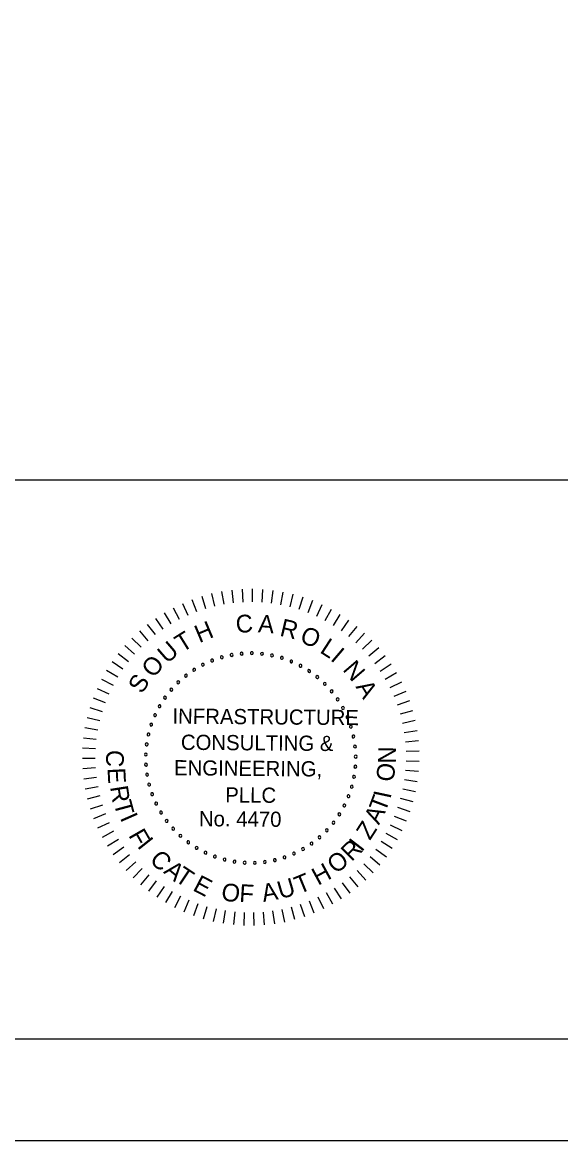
# Model space of a CAD drawing. Extents: x 1970675.2 to 1970711.3, y 796145.2 to 796167.2.
# Drawn here: x 1970700.45 to 1970703.09, y 796145.25 to 796150.75 of the extents above; entities that cross this region are included whole.
import ezdxf

# ---------------------------------------------------------------- set-up
doc = ezdxf.new("R2010")
doc.units = 0
for name, color, linetype in [('BR_BORDER LINES', 7, 'Continuous'), ('BR_TEXT', 7, 'Continuous'), ('Level 31', 7, 'Continuous')]:
    doc.layers.add(name, color=color, linetype=linetype)

msp = doc.modelspace()

# ---------------------------------------------------------------- linework, layer by layer
at = {"layer": 'BR_BORDER LINES'}
for p, q in [((1970697.8703, 796148.4964), (1970703.2355, 796148.4964)), ((1970677.0698, 796145.7463), (1970710.7358, 796145.7463))]:
    msp.add_line(p, q, dxfattribs=at)
at = {"layer": 'BR_TEXT'}
for p, q in [((1970701.4262, 796147.9473), (1970701.4372, 796147.8846)), ((1970701.4761, 796147.9545), (1970701.4834, 796147.8913)), ((1970701.5265, 796147.9587), (1970701.5298, 796147.8951)), ((1970701.5769, 796147.9597), (1970701.5764, 796147.8961)), ((1970701.6274, 796147.9577), (1970701.623, 796147.8942)), ((1970701.6776, 796147.9526), (1970701.6693, 796147.8895)), ((1970701.2802, 796147.9077), (1970701.3025, 796147.8481)), ((1970701.328, 796147.9239), (1970701.3466, 796147.863)), ((1970701.3767, 796147.9371), (1970701.3916, 796147.8752)), ((1970701.7274, 796147.9445), (1970701.7153, 796147.882)), ((1970701.7767, 796147.9333), (1970701.7608, 796147.8717)), ((1970701.8251, 796147.9192), (1970701.8055, 796147.8586)), ((1970701.8726, 796147.9021), (1970701.8494, 796147.8428)), ((1970701.1439, 796147.8422), (1970701.1766, 796147.7876)), ((1970701.1879, 796147.8668), (1970701.2173, 796147.8103)), ((1970701.2334, 796147.8887), (1970701.2593, 796147.8305)), ((1970701.919, 796147.8822), (1970701.8922, 796147.8244)), ((1970701.9641, 796147.8594), (1970701.9338, 796147.8034)), ((1970701.0606, 796147.7852), (1970701.0998, 796147.735)), ((1970701.1014, 796147.8149), (1970701.1374, 796147.7625)), ((1970702.0077, 796147.834), (1970701.974, 796147.78)), ((1970702.0497, 796147.8059), (1970702.0128, 796147.7541)), ((1970701.0217, 796147.7529), (1970701.0639, 796147.7052)), ((1970702.0899, 796147.7754), (1970702.0499, 796147.7259)), ((1970702.1281, 796147.7424), (1970702.0852, 796147.6954)), ((1970700.9502, 796147.6817), (1970700.9979, 796147.6395)), ((1970700.9849, 796147.7184), (1970701.0299, 796147.6734)), ((1970702.1643, 796147.7072), (1970702.1186, 796147.6629)), ((1970700.9179, 796147.643), (1970700.968, 796147.6037)), ((1970702.1982, 796147.6699), (1970702.1499, 796147.6284)), ((1970702.2299, 796147.6305), (1970702.1791, 796147.5921)), ((1970700.8879, 796147.6023), (1970700.9404, 796147.5662)), ((1970702.259, 796147.5893), (1970702.206, 796147.5541)), ((1970700.8358, 796147.5159), (1970700.8922, 796147.4865)), ((1970700.8605, 796147.5599), (1970700.9151, 796147.5271)), ((1970702.2856, 796147.5464), (1970702.2305, 796147.5145)), ((1970700.8137, 796147.4705), (1970700.8719, 796147.4445)), ((1970702.3095, 796147.5019), (1970702.2526, 796147.4734)), ((1970702.3307, 796147.4561), (1970702.2722, 796147.4311)), ((1970700.7945, 796147.4238), (1970700.8541, 796147.4014)), ((1970702.3491, 796147.4091), (1970702.2891, 796147.3877)), ((1970700.7782, 796147.3761), (1970700.839, 796147.3574)), ((1970702.3645, 796147.361), (1970702.3033, 796147.3433)), ((1970700.7648, 796147.3274), (1970700.8267, 796147.3124)), ((1970702.377, 796147.3121), (1970702.3148, 796147.2982)), ((1970700.7543, 796147.278), (1970700.817, 796147.2668)), ((1970702.3864, 796147.2625), (1970702.3236, 796147.2524)), ((1970700.7426, 796147.1777), (1970700.8062, 796147.1743)), ((1970700.747, 796147.228), (1970700.8102, 796147.2207)), ((1970702.3929, 796147.2124), (1970702.3295, 796147.2062)), ((1970700.7414, 796147.1273), (1970700.8051, 796147.1277)), ((1970702.3963, 796147.1621), (1970702.3326, 796147.1597)), ((1970700.7432, 796147.0768), (1970700.8067, 796147.0812)), ((1970702.3965, 796147.1116), (1970702.3329, 796147.1131)), ((1970700.7481, 796147.0266), (1970700.8113, 796147.0348)), ((1970702.3879, 796147.011), (1970702.3249, 796147.0203)), ((1970702.3938, 796147.0612), (1970702.3303, 796147.0666)), ((1970700.7561, 796146.9767), (1970700.8186, 796146.9888)), ((1970702.379, 796146.9613), (1970702.3167, 796146.9744)), ((1970700.7671, 796146.9275), (1970700.8287, 796146.9433)), ((1970702.3671, 796146.9123), (1970702.3057, 796146.9291)), ((1970700.781, 796146.8789), (1970700.8416, 796146.8985)), ((1970700.7979, 796146.8314), (1970700.8572, 796146.8546)), ((1970702.3522, 796146.864), (1970702.2919, 796146.8846)), ((1970700.8177, 796146.7849), (1970700.8755, 796146.8117)), ((1970702.3138, 796146.7707), (1970702.2564, 796146.7985)), ((1970702.3344, 796146.8168), (1970702.2755, 796146.841)), ((1970700.8403, 796146.7397), (1970700.8963, 796146.77)), ((1970702.2904, 796146.726), (1970702.2348, 796146.7572)), ((1970700.8655, 796146.696), (1970700.9196, 796146.7297)), ((1970700.8934, 796146.654), (1970700.9453, 796146.6908)), ((1970702.2643, 796146.6828), (1970702.2107, 796146.7173)), ((1970700.9238, 796146.6137), (1970700.9734, 796146.6536)), ((1970702.2044, 796146.6015), (1970702.1555, 796146.6423)), ((1970702.2356, 796146.6412), (1970702.1843, 796146.6789)), ((1970700.9566, 796146.5753), (1970701.0037, 796146.6182)), ((1970700.9917, 796146.539), (1970701.0361, 796146.5847)), ((1970702.1351, 796146.5281), (1970702.0915, 796146.5745)), ((1970702.1709, 796146.5638), (1970702.1245, 796146.6074)), ((1970701.0289, 796146.5049), (1970701.0704, 796146.5532)), ((1970701.0682, 796146.4731), (1970701.1066, 796146.5239)), ((1970702.0973, 796146.4948), (1970702.0566, 796146.5437)), ((1970701.1093, 796146.4438), (1970701.1446, 796146.4968)), ((1970701.1521, 796146.4171), (1970701.1841, 796146.4721)), ((1970701.9725, 796146.4093), (1970701.9414, 796146.4648)), ((1970702.0158, 796146.4352), (1970701.9813, 796146.4888)), ((1970702.0574, 796146.4637), (1970702.0198, 796146.5151)), ((1970701.1965, 796146.393), (1970701.225, 796146.4499)), ((1970701.2422, 796146.3716), (1970701.2673, 796146.4302)), ((1970701.2892, 796146.3531), (1970701.3106, 796146.4131)), ((1970701.8342, 796146.3479), (1970701.8137, 796146.4082)), ((1970701.8815, 796146.3656), (1970701.8574, 796146.4245)), ((1970701.9276, 796146.386), (1970701.9, 796146.4434)), ((1970701.3372, 796146.3375), (1970701.3549, 796146.3986)), ((1970701.386, 796146.3248), (1970701.4001, 796146.3869)), ((1970701.4356, 796146.3152), (1970701.4458, 796146.378)), ((1970701.4856, 796146.3086), (1970701.492, 796146.3719)), ((1970701.536, 796146.305), (1970701.5385, 796146.3686)), ((1970701.5865, 796146.3045), (1970701.5851, 796146.3682)), ((1970701.6369, 796146.3071), (1970701.6316, 796146.3706)), ((1970701.6871, 796146.3128), (1970701.6779, 796146.3758)), ((1970701.7368, 796146.3215), (1970701.7238, 796146.3838)), ((1970701.7859, 796146.3332), (1970701.7691, 796146.3947))]:
    msp.add_line(p, q, dxfattribs=at)
for centre, start, end in [((1970701.4268, 796147.6235), 16.1422, 196.1422), ((1970701.4268, 796147.6235), 196.1422, 16.1422), ((1970701.4753, 796147.635), 10.6038, 190.6038), ((1970701.4753, 796147.635), 190.6038, 10.6038), ((1970701.5247, 796147.6417), 5.0653, 185.0653), ((1970701.5247, 796147.6417), 185.0653, 5.0653), ((1970701.5745, 796147.6436), 359.5268, 179.5268), ((1970701.5745, 796147.6436), 179.5268, 359.5268), ((1970701.6242, 796147.6407), 173.9884, 353.9884), ((1970701.6242, 796147.6407), 353.9884, 173.9884), ((1970701.6735, 796147.6329), 168.4499, 348.4499), ((1970701.6735, 796147.6329), 348.4499, 168.4499), ((1970701.7217, 796147.6205), 162.9114, 342.9114), ((1970701.7217, 796147.6205), 342.9114, 162.9114), ((1970701.291, 796147.5621), 32.7576, 212.7576), ((1970701.291, 796147.5621), 212.7576, 32.7576), ((1970701.3343, 796147.587), 27.2191, 207.2191), ((1970701.3343, 796147.587), 207.2191, 27.2191), ((1970701.3797, 796147.6075), 21.6807, 201.6807), ((1970701.3797, 796147.6075), 201.6807, 21.6807), ((1970701.7686, 796147.6035), 157.373, 337.373), ((1970701.7686, 796147.6035), 337.373, 157.373), ((1970701.8135, 796147.582), 151.8345, 331.8345), ((1970701.8135, 796147.582), 331.8345, 151.8345), ((1970701.8562, 796147.5563), 326.2961, 146.2961), ((1970701.2128, 796147.5006), 43.8345, 223.8345), ((1970701.2504, 796147.5333), 38.2961, 218.2961), ((1970701.2504, 796147.5333), 218.2961, 38.2961), ((1970701.8562, 796147.5563), 146.2961, 326.2961), ((1970701.8962, 796147.5266), 140.7576, 320.7576), ((1970701.8962, 796147.5266), 320.7576, 140.7576), ((1970701.1785, 796147.4645), 49.373, 229.373), ((1970701.1785, 796147.4645), 229.373, 49.373), ((1970701.2128, 796147.5006), 223.8345, 43.8345), ((1970701.9332, 796147.4932), 135.2191, 315.2191), ((1970701.9332, 796147.4932), 315.2191, 135.2191), ((1970701.9668, 796147.4564), 129.6807, 309.6807), ((1970701.9668, 796147.4564), 309.6807, 129.6807), ((1970701.1478, 796147.4252), 54.9114, 234.9114), ((1970701.1478, 796147.4252), 234.9114, 54.9114), ((1970701.9966, 796147.4165), 124.1422, 304.1422), ((1970701.9966, 796147.4165), 304.1422, 124.1422), ((1970701.0986, 796147.3387), 65.9884, 245.9884), ((1970701.0986, 796147.3387), 245.9884, 65.9884), ((1970701.1211, 796147.3831), 60.4499, 240.4499), ((1970701.1211, 796147.3831), 240.4499, 60.4499), ((1970702.0225, 796147.3739), 118.6038, 298.6038), ((1970702.0225, 796147.3739), 298.6038, 118.6038), ((1970701.0804, 796147.2923), 71.5268, 251.5268), ((1970701.0804, 796147.2923), 251.5268, 71.5268), ((1970702.0441, 796147.329), 113.0653, 293.0653), ((1970702.0441, 796147.329), 293.0653, 113.0653), ((1970702.0613, 796147.2822), 107.5268, 287.5268), ((1970702.0613, 796147.2822), 287.5268, 107.5268), ((1970701.0668, 796147.2443), 77.0653, 257.0653), ((1970701.0668, 796147.2443), 257.0653, 77.0653), ((1970702.0739, 796147.234), 101.9884, 281.9884), ((1970702.0739, 796147.234), 281.9884, 101.9884), ((1970701.0579, 796147.1953), 82.6038, 262.6038), ((1970701.0579, 796147.1953), 262.6038, 82.6038), ((1970702.0818, 796147.1848), 96.4499, 276.4499), ((1970702.0818, 796147.1848), 276.4499, 96.4499), ((1970701.0538, 796147.1456), 88.1422, 268.1422), ((1970701.0538, 796147.1456), 268.1422, 88.1422), ((1970702.0849, 796147.1351), 90.9114, 270.9114), ((1970702.0849, 796147.1351), 270.9114, 90.9114), ((1970701.0545, 796147.0958), 93.6807, 273.6807), ((1970701.0545, 796147.0958), 273.6807, 93.6807), ((1970702.0832, 796147.0853), 85.373, 265.373), ((1970702.0832, 796147.0853), 265.373, 85.373), ((1970701.06, 796147.0463), 99.2191, 279.2191), ((1970701.06, 796147.0463), 279.2191, 99.2191), ((1970702.0766, 796147.0359), 79.8345, 259.8345), ((1970702.0766, 796147.0359), 259.8345, 79.8345), ((1970701.0703, 796146.9975), 104.7576, 284.7576), ((1970701.0703, 796146.9975), 284.7576, 104.7576), ((1970701.0852, 796146.95), 290.2961, 110.2961), ((1970702.0654, 796146.9873), 74.2961, 254.2961), ((1970702.0654, 796146.9873), 254.2961, 74.2961), ((1970701.0852, 796146.95), 110.2961, 290.2961), ((1970701.1046, 796146.9041), 115.8345, 295.8345), ((1970701.1046, 796146.9041), 295.8345, 115.8345), ((1970702.0291, 796146.8946), 63.2191, 243.2191), ((1970702.0495, 796146.9401), 68.7576, 248.7576), ((1970702.0495, 796146.9401), 248.7576, 68.7576), ((1970701.1284, 796146.8603), 121.373, 301.373), ((1970701.1284, 796146.8603), 301.373, 121.373), ((1970702.0045, 796146.8513), 57.6807, 237.6807), ((1970702.0045, 796146.8513), 237.6807, 57.6807), ((1970702.0291, 796146.8946), 243.2191, 63.2191), ((1970701.1563, 796146.819), 126.9114, 306.9114), ((1970701.1563, 796146.819), 306.9114, 126.9114), ((1970701.9758, 796146.8106), 52.1422, 232.1422), ((1970701.9758, 796146.8106), 232.1422, 52.1422), ((1970701.188, 796146.7806), 132.4499, 312.4499), ((1970701.188, 796146.7806), 312.4499, 132.4499), ((1970701.2233, 796146.7454), 137.9884, 317.9884), ((1970701.2233, 796146.7454), 317.9884, 137.9884), ((1970701.9072, 796146.7384), 41.0653, 221.0653), ((1970701.9072, 796146.7384), 221.0653, 41.0653), ((1970701.9432, 796146.7728), 46.6038, 226.6038), ((1970701.9432, 796146.7728), 226.6038, 46.6038), ((1970701.2618, 796146.7138), 143.5268, 323.5268), ((1970701.2618, 796146.7138), 323.5268, 143.5268), ((1970701.3032, 796146.6861), 149.0653, 329.0653), ((1970701.3032, 796146.6861), 329.0653, 149.0653), ((1970701.8261, 796146.6807), 29.9884, 209.9884), ((1970701.8261, 796146.6807), 209.9884, 29.9884), ((1970701.8681, 796146.7076), 35.5268, 215.5268), ((1970701.8681, 796146.7076), 215.5268, 35.5268), ((1970701.3471, 796146.6625), 154.6038, 334.6038), ((1970701.3471, 796146.6625), 334.6038, 154.6038), ((1970701.3931, 796146.6432), 160.1422, 340.1422), ((1970701.3931, 796146.6432), 340.1422, 160.1422), ((1970701.4407, 796146.6285), 165.6807, 345.6807), ((1970701.4407, 796146.6285), 345.6807, 165.6807), ((1970701.6875, 796146.6259), 13.373, 193.373), ((1970701.6875, 796146.6259), 193.373, 13.373), ((1970701.7354, 796146.6397), 18.9114, 198.9114), ((1970701.7354, 796146.6397), 198.9114, 18.9114), ((1970701.7817, 796146.658), 24.4499, 204.4499), ((1970701.7817, 796146.658), 204.4499, 24.4499), ((1970701.4895, 796146.6184), 171.2191, 351.2191), ((1970701.4895, 796146.6184), 351.2191, 171.2191), ((1970701.539, 796146.6131), 356.7576, 176.7576), ((1970701.539, 796146.6131), 176.7576, 356.7576), ((1970701.5889, 796146.6126), 2.2961, 182.2961), ((1970701.5889, 796146.6126), 182.2961, 2.2961), ((1970701.6385, 796146.6169), 7.8345, 187.8345), ((1970701.6385, 796146.6169), 187.8345, 7.8345)]:
    msp.add_arc(centre, 0.00701, start, end, dxfattribs=at)
at = {"layer": 'Level 31'}
msp.add_lwpolyline([(1970675.2365, 796145.2464), (1970711.2364, 796145.2464), (1970711.2364, 796167.2463), (1970675.2365, 796167.2463)], close=True, dxfattribs=at)

# ---------------------------------------------------------------- texts
at = {"layer": 'BR_TEXT'}
for s, height, rotation, p in [('H', 0.0872, 22.7882, (1970701.3162, 796147.6927)), ('C', 0.0872, 4.7281, (1970701.499, 796147.7421)), ('A', 0.0872, 355.6981, (1970701.6035, 796147.7471)), ('R', 0.0872, 346.6681, (1970701.7077, 796147.7301)), ('T', 0.0872, 31.8182, (1970701.2313, 796147.6451)), ('O', 0.0872, 337.638, (1970701.8055, 796147.7003)), ('U', 0.0872, 40.8482, (1970701.158, 796147.589)), ('L', 0.0872, 327.108, (1970701.9043, 796147.6498)), ('O', 0.0872, 49.8782, (1970701.091, 796147.518)), ('I', 0.0872, 319.578, (1970701.9569, 796147.612)), ('N', 0.0872, 310.548, (1970702.0177, 796147.5612)), ('S', 0.0872, 58.9083, (1970701.0356, 796147.4398)), ('A', 0.0872, 301.5179, (1970702.0828, 796147.4788)), ('INFRASTRUCTURE', 0.074771, 359.5268, (1970701.1842, 796147.2972)), ('CONSULTING &', 0.074771, 359.5268, (1970701.2255, 796147.1686)), ('C', 0.0872, 267.025, (1970700.8606, 796147.1698)), ('N', 0.0872, 89.2085, (1970702.2821, 796147.1001)), ('E', 0.0872, 273.025, (1970700.865, 796147.0783)), ('ENGINEERING,', 0.074771, 359.5268, (1970701.1919, 796147.0432)), ('O', 0.0872, 83.2085, (1970702.271, 796147.0086)), ('R', 0.0872, 279.025, (1970700.8778, 796146.986)), ('PLLC', 0.07477, 359.5268, (1970701.4436, 796146.9096)), ('I', 0.0872, 77.9093, (1970702.2555, 796146.9243)), ('T', 0.0872, 285.025, (1970700.8952, 796146.9072)), ('T', 0.0872, 69.3954, (1970702.2298, 796146.8568)), ('I', 0.0872, 293.7713, (1970700.9249, 796146.8341)), ('No. 4470', 0.07477, 359.5268, (1970701.3141, 796146.7927)), ('A', 0.0872, 63.3954, (1970702.199, 796146.7965)), ('Z', 0.0872, 57.3954, (1970702.1551, 796146.7202)), ('F', 0.0872, 299.7713, (1970700.9661, 796146.748)), ('I', 0.0872, 308.5268, (1970701.0082, 796146.6942)), ('R', 0.0872, 44.5268, (1970702.0647, 796146.6152)), ('I', 0.0872, 52.3339, (1970702.1141, 796146.6625)), ('C', 0.0872, 314.5268, (1970701.0675, 796146.6241)), ('O', 0.0872, 38.5268, (1970701.9881, 796146.5552)), ('A', 0.0872, 320.5268, (1970701.1367, 796146.5655)), ('T', 0.0872, 326.5268, (1970701.1911, 796146.527)), ('H', 0.0872, 28.5268, (1970701.9, 796146.4992)), ('E', 0.0872, 332.5268, (1970701.2797, 796146.4792)), ('U', 0.0872, 16.5268, (1970701.7151, 796146.4331)), ('T', 0.0872, 22.5268, (1970701.8068, 796146.4575)), ('O', 0.0872, 350.5268, (1970701.4198, 796146.4304)), ('F', 0.0872, 356.5268, (1970701.5113, 796146.4212)), ('A', 0.0872, 10.5268, (1970701.6312, 796146.4196))]:
    msp.add_text(s, height=height, rotation=rotation, dxfattribs=at).set_placement(p)

doc.saveas('drawing.dxf')
